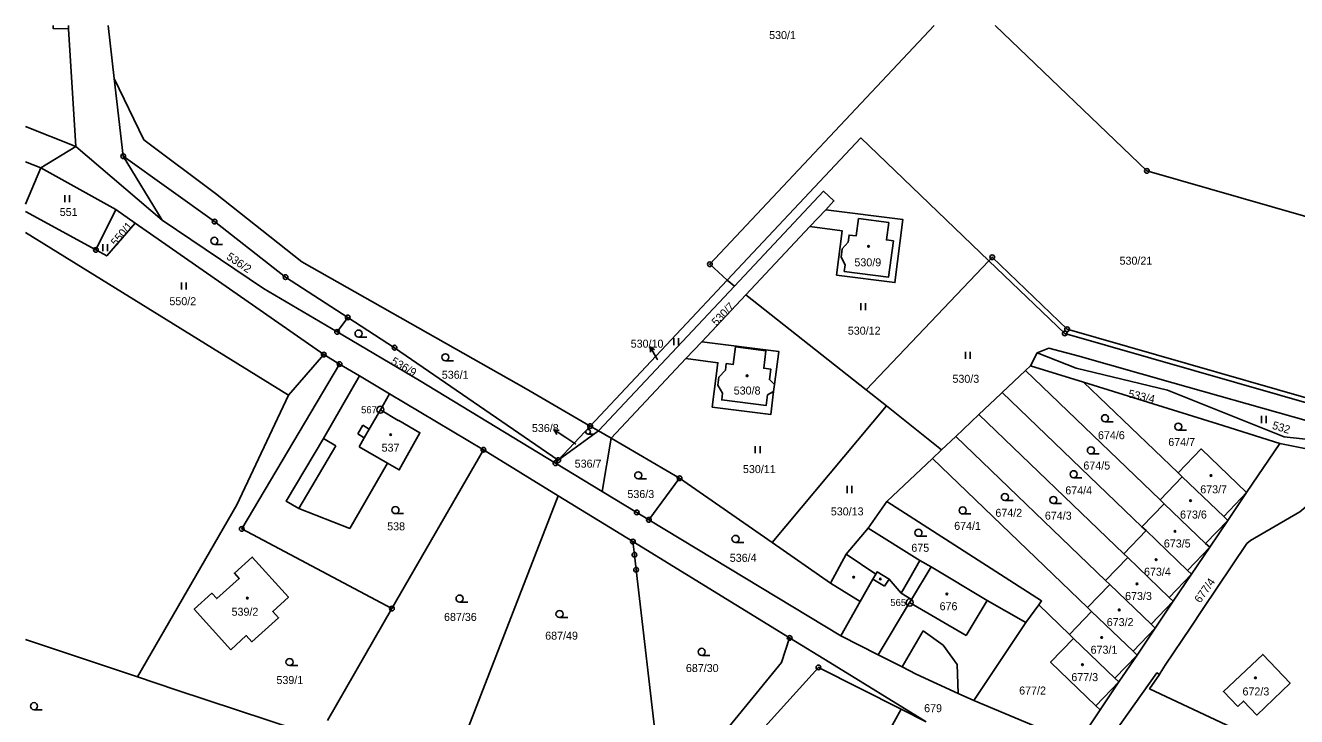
# Model space of a CAD drawing. Extents: x -749778 to -749372, y -967291 to -966955.
# Drawn here: x -749777.6 to -749507.7, y -967101.9 to -966955.1 of the extents above; entities that cross this region are included whole.
import ezdxf

# ---------------------------------------------------------------- set-up
doc = ezdxf.new("R2010")
doc.units = 0
for name, color, linetype in [('Hranice parcel', 7, 'Continuous'), ('Parcelní čísla', 7, 'Continuous'), ('Pop  PČ popisy', 7, 'Continuous'), ('Vnitřní kresba', 7, 'Continuous'), ('Značky bodu BP', 7, 'Continuous'), ('Značky budov', 7, 'Continuous'), ('Značky kultur', 7, 'Continuous')]:
    doc.layers.add(name, color=color, linetype=linetype)

msp = doc.modelspace()

# ---------------------------------------------------------------- linework, layer by layer
at = {"layer": 'Hranice parcel'}
for p, q in [((-749768.49, -966955.06), (-749768.51, -966955.82)), ((-749768.51, -966955.82), (-749766.93, -966980.78)), ((-749756.87, -966982.87), (-749758.78, -966966.32)), ((-749766.93, -966980.78), (-749777.63, -966976.54)), ((-749774.34, -966985.3), (-749766.93, -966980.78)), ((-749766.93, -966980.78), (-749748.6, -966996.42)), ((-749748.6, -966996.42), (-749756.87, -966982.87)), ((-749774.34, -966985.3), (-749777.63, -966984.05)), ((-749758.43, -966994.19), (-749774.34, -966985.3)), ((-749758.43, -966994.19), (-749762.66, -967002.76)), ((-749754.33, -966997.05), (-749758.43, -966994.19)), ((-749611.05, -966997.82), (-749607.66, -966994.22)), ((-749714.28, -967025), (-749754.33, -966997.05)), ((-749721.74, -967033.62), (-749777.63, -966999.06)), ((-749624.66, -967012.31), (-749611.05, -966997.82)), ((-749573, -967005.05), (-749599.06, -967032.48)), ((-749657.69, -967040.19), (-749628.61, -967009.22)), ((-749627.02, -967010.45), (-749655.92, -967041.22)), ((-749627.02, -967010.45), (-749628.61, -967009.22)), ((-749634, -967022.26), (-749624.66, -967012.31)), ((-749599.06, -967032.48), (-749624.66, -967012.31)), ((-749711.43, -967020.19), (-749709.16, -967017.1)), ((-749637.38, -967025.86), (-749634, -967022.26)), ((-749721.74, -967033.62), (-749714.28, -967025)), ((-749714.28, -967025), (-749710.9, -967027.02)), ((-749706.67, -967029.54), (-749710.9, -967027.02)), ((-749653.26, -967042.77), (-749637.38, -967025.86)), ((-749564.16, -967027.37), (-749562.74, -967024.63)), ((-749700.29, -967033.34), (-749706.67, -967029.54)), ((-749570.18, -967033.07), (-749565.25, -967028.4)), ((-749565.25, -967028.4), (-749564.16, -967027.37)), ((-749536.64, -967055.87), (-749565.25, -967028.4)), ((-749564.16, -967027.37), (-749552.89, -967030.87)), ((-749532.8, -967050.13), (-749552.89, -967030.87)), ((-749680.37, -967045.22), (-749700.29, -967033.34)), ((-749599.06, -967032.48), (-749594.75, -967035.91)), ((-749540.5, -967061.59), (-749570.18, -967033.07)), ((-749619.07, -967064.92), (-749594.75, -967035.91)), ((-749594.75, -967035.91), (-749583.06, -967045.24)), ((-749580.06, -967042.41), (-749575.13, -967037.74)), ((-749544.33, -967067.31), (-749575.13, -967037.74)), ((-749664.47, -967047.42), (-749657.69, -967040.19)), ((-749655.92, -967041.22), (-749657.69, -967040.19)), ((-749655.92, -967041.22), (-749664.47, -967047.42)), ((-749655.92, -967041.22), (-749653.26, -967042.77)), ((-749653.26, -967042.77), (-749655.12, -967054.12)), ((-749638.69, -967051.26), (-749653.26, -967042.77)), ((-749583.06, -967045.24), (-749580.06, -967042.41)), ((-749548.22, -967073.01), (-749580.06, -967042.41)), ((-749699.81, -967078.98), (-749680.37, -967045.22)), ((-749680.37, -967045.22), (-749664.5, -967054.98)), ((-749583.06, -967045.24), (-749585.01, -967047.08)), ((-749518.29, -967054.31), (-749511.23, -967043.86)), ((-749664.47, -967047.42), (-749665.08, -967048.07)), ((-749655.12, -967054.12), (-749665.08, -967048.07)), ((-749585.01, -967047.08), (-749594.68, -967056.22)), ((-749552.05, -967078.75), (-749585.01, -967047.08)), ((-749645.2, -967060.11), (-749638.69, -967051.26)), ((-749619.07, -967064.92), (-749638.69, -967051.26)), ((-749531.93, -967050.96), (-749536.64, -967055.87)), ((-749532.8, -967050.13), (-749531.93, -967050.96)), ((-749684.12, -967105.59), (-749664.5, -967054.98)), ((-749664.5, -967054.98), (-749648.62, -967064.74)), ((-749535.77, -967056.7), (-749540.5, -967061.59)), ((-749536.64, -967055.87), (-749535.77, -967056.7)), ((-749522.26, -967060.23), (-749518.29, -967054.31)), ((-749604.44, -967084.74), (-749645.2, -967060.11)), ((-749540.5, -967061.59), (-749539.64, -967062.41)), ((-749526.12, -967065.95), (-749522.26, -967060.23)), ((-749648.62, -967064.74), (-749615.32, -967085.21)), ((-749539.64, -967062.41), (-749544.33, -967067.31)), ((-749606.68, -967073.54), (-749619.07, -967064.92)), ((-749603.32, -967067.37), (-749606.68, -967073.54)), ((-749544.33, -967067.31), (-749543.47, -967068.14)), ((-749529.98, -967071.67), (-749526.12, -967065.95)), ((-749543.47, -967068.14), (-749548.22, -967073.01)), ((-749533.84, -967077.4), (-749529.98, -967071.67)), ((-749547.35, -967073.84), (-749552.05, -967078.75)), ((-749548.22, -967073.01), (-749547.35, -967073.84)), ((-749565.15, -967081.89), (-749562.42, -967078.16)), ((-749562.42, -967078.16), (-749555.87, -967084.45)), ((-749537.69, -967083.12), (-749533.84, -967077.4)), ((-749699.81, -967078.98), (-749713.49, -967102.74)), ((-749551.19, -967079.58), (-749555.87, -967084.45)), ((-749552.05, -967078.75), (-749551.19, -967079.58)), ((-749576.24, -967098.5), (-749565.15, -967081.89)), ((-749541.54, -967088.85), (-749537.69, -967083.12)), ((-749555.87, -967084.45), (-749555.02, -967085.29)), ((-749545.4, -967094.56), (-749541.54, -967088.85)), ((-749549.38, -967100.48), (-749545.4, -967094.56)), ((-749576.24, -967098.5), (-749554.23, -967107.67)), ((-749586.36, -967103.02), (-749591.67, -967100.33))]:
    msp.add_line(p, q, dxfattribs=at)
for points in [[(-749768.51, -966955.82), (-749771.73, -966955.75), (-749771.71, -966955.06)], [(-749758.78, -966966.32), (-749760.08, -966955.06)], [(-749628.61, -967009.22), (-749632.26, -967005.8), (-749584.62, -966955.06)], [(-749571.65, -966955.06), (-749539.45, -966985.97), (-749459.63, -967008.89), (-749477.4, -967037.32)], [(-749758.78, -966966.32), (-749752.45, -966979.37), (-749737.29, -966990.76), (-749718.94, -967005.3), (-749671.29, -967032.27), (-749657.69, -967040.19)], [(-749573, -967005.05), (-749600.19, -966978.95), (-749628.61, -967009.22)], [(-749756.87, -966982.87), (-749737.45, -966996.74), (-749722.38, -967008.55), (-749709.16, -967017.1)], [(-749777.63, -966993.01), (-749774.34, -966985.3)], [(-749607.66, -966994.22), (-749605.92, -966992.36), (-749608.11, -966990.31), (-749627.02, -967010.45)], [(-749762.66, -967002.76), (-749777.63, -966994.6)], [(-749611.05, -966997.82), (-749604.17, -966998.69), (-749605.37, -967008.12), (-749592.97, -967009.7), (-749591.26, -966996.3), (-749607.66, -966994.22)], [(-749762.66, -967002.76), (-749760.36, -967004.02), (-749754.33, -966997.05)], [(-749711.43, -967020.19), (-749727.04, -967010.95), (-749748.6, -966996.42)], [(-749573, -967005.05), (-749572.31, -967004.33), (-749556.39, -967019.6), (-749480.03, -967041.53), (-749477.4, -967037.32)], [(-749474.68, -967044.11), (-749556.9, -967020.49), (-749573, -967005.05)], [(-749709.16, -967017.1), (-749699.22, -967023.53), (-749664.47, -967047.42)], [(-749665.08, -967048.07), (-749693.94, -967030.54), (-749711.43, -967020.19)], [(-749637.38, -967025.86), (-749630.55, -967026.73), (-749631.75, -967036.16), (-749619.35, -967037.74), (-749618.72, -967032.84), (-749618.54, -967031.36), (-749617.64, -967024.34), (-749634, -967022.26)], [(-749562.74, -967024.63), (-749560.29, -967023.62), (-749554.11, -967025.29), (-749533.97, -967031.01), (-749482.86, -967045.42)], [(-749710.9, -967027.02), (-749731.68, -967062.04), (-749699.81, -967078.98)], [(-749562.74, -967024.63), (-749554.44, -967027.88), (-749535.11, -967032.59), (-749510.28, -967042.45), (-749482.86, -967045.42)], [(-749706.67, -967029.54), (-749714.33, -967042.83), (-749722.22, -967056.16), (-749719.59, -967057.72), (-749708.76, -967061.94), (-749700.71, -967048.1), (-749698.23, -967049.52), (-749693.83, -967041.62), (-749698.3, -967038.99), (-749698.47, -967039.04), (-749702.24, -967036.72), (-749700.29, -967033.34)], [(-749552.89, -967030.87), (-749524.47, -967039.74), (-749511.23, -967043.86)], [(-749753.84, -967093.49), (-749732.73, -967056.95), (-749721.74, -967033.62)], [(-749575.13, -967037.74), (-749570.49, -967033.35), (-749570.18, -967033.07)], [(-749518.29, -967054.31), (-749527.96, -967045.04), (-749532.8, -967050.13)], [(-749511.23, -967043.86), (-749503.78, -967045.37), (-749490.3, -967048.1), (-749484.05, -967051.31)], [(-749522.26, -967060.23), (-749523.13, -967059.41), (-749531.93, -967050.96)], [(-749456.84, -967065.27), (-749475.82, -967057.43), (-749489.74, -967052.51), (-749500.28, -967053.21), (-749501.83, -967053.4), (-749502.46, -967054.34), (-749503.87, -967055.82), (-749506.95, -967058.39), (-749517.45, -967064.49), (-749518.23, -967065.16), (-749527.61, -967079.16), (-749530.11, -967082.89), (-749535.6, -967090.98), (-749536.66, -967092.72), (-749536.81, -967092.95)], [(-749645.2, -967060.11), (-749647.8, -967058.54), (-749655.12, -967054.12)], [(-749594.68, -967056.22), (-749598.63, -967061.85), (-749603.32, -967067.37)], [(-749594.68, -967056.22), (-749561.83, -967077.35), (-749562.42, -967078.16)], [(-749526.12, -967065.95), (-749526.97, -967065.13), (-749535.77, -967056.7)], [(-749648.62, -967064.74), (-749648.3, -967067.53), (-749647.94, -967070.71), (-749643.43, -967109.15)], [(-749529.98, -967071.67), (-749530.84, -967070.85), (-749539.64, -967062.41)], [(-749603.32, -967067.37), (-749597.01, -967071.63), (-749596.76, -967071.19), (-749594.16, -967072.69), (-749591.62, -967075.7), (-749589.79, -967072.47), (-749587.69, -967068.76), (-749585.3, -967070.11), (-749573.36, -967077.28), (-749565.15, -967081.89)], [(-749734.04, -967087.7), (-749741.77, -967079.12), (-749738.02, -967075.7), (-749737, -967076.84), (-749732.23, -967072.54), (-749733.26, -967071.41), (-749729.47, -967068.01), (-749721.76, -967076.51), (-749725.09, -967079.58), (-749723.88, -967080.9), (-749729.51, -967086), (-749730.74, -967084.72), (-749734.04, -967087.7)], [(-749533.84, -967077.4), (-749534.69, -967076.58), (-749543.47, -967068.14)], [(-749606.68, -967073.54), (-749600.38, -967077.49), (-749604.44, -967084.74)], [(-749537.69, -967083.12), (-749538.56, -967082.3), (-749547.35, -967073.84)], [(-749541.54, -967088.85), (-749542.39, -967088.02), (-749551.19, -967079.58)], [(-749777.63, -967085.52), (-749753.84, -967093.49)], [(-749632.88, -967109.8), (-749617.06, -967090.42), (-749615.32, -967085.21)], [(-749615.32, -967085.21), (-749606.8, -967090.45), (-749586.36, -967103.02)], [(-749604.44, -967084.74), (-749596.53, -967088.77), (-749591.42, -967091.37), (-749588.45, -967092.89), (-749579.53, -967096.99), (-749576.24, -967098.5)], [(-749549.38, -967100.48), (-749550.27, -967099.62), (-749559.92, -967090.32), (-749555.02, -967085.29)], [(-749555.02, -967085.29), (-749546.27, -967093.74), (-749545.4, -967094.56)], [(-749520.16, -967099.8), (-749523.2, -967096.56), (-749514.83, -967088.7), (-749509.04, -967094.79), (-749516.12, -967101.59), (-749518.91, -967098.62), (-749520.16, -967099.8)], [(-749624.65, -967108.54), (-749609.2, -967091.46), (-749591.67, -967100.33)], [(-749716.74, -967108.38), (-749719.68, -967104.83), (-749745.68, -967096.2), (-749753.84, -967093.49)], [(-749536.81, -967092.95), (-749537.33, -967092.65), (-749549.42, -967109.68)], [(-749536.81, -967092.95), (-749538.87, -967096), (-749521.44, -967104.24), (-749491.04, -967118.52)], [(-749591.67, -967100.33), (-749597.57, -967111.08), (-749601.91, -967114.2), (-749600.64, -967116.26), (-749606.62, -967124.91)], [(-749554.23, -967107.67), (-749553.8, -967107.04), (-749549.38, -967100.48)]]:
    msp.add_lwpolyline(points, dxfattribs=at)
at = {"layer": 'Pop  PČ popisy'}
for p, q in [((-749643.44, -967025.94), (-749644.94, -967023.34)), ((-749644.94, -967023.34), (-749644.01, -967023.96)), ((-749644.94, -967023.34), (-749644.87, -967024.46)), ((-749643.35, -967026.09), (-749643.44, -967025.94)), ((-749662.84, -967042.65), (-749665.36, -967041.02)), ((-749665.36, -967041.02), (-749664.24, -967041.14)), ((-749665.36, -967041.02), (-749664.79, -967041.98)), ((-749660.71, -967044.04), (-749662.84, -967042.65))]:
    msp.add_line(p, q, dxfattribs=at)
at = {"layer": 'Vnitřní kresba'}
for p, q in [((-749704.61, -967040.83), (-749702.24, -967036.72)), ((-749707.06, -967041.87), (-749706, -967040.03)), ((-749706, -967040.03), (-749704.61, -967040.83)), ((-749714.33, -967042.83), (-749711.7, -967044.39)), ((-749705.67, -967042.67), (-749707.06, -967041.87)), ((-749706.78, -967044.6), (-749705.67, -967042.67)), ((-749704.61, -967040.83), (-749705.67, -967042.67)), ((-749711.7, -967044.39), (-749719.59, -967057.72)), ((-749700.71, -967048.1), (-749706.78, -967044.6)), ((-749518.29, -967054.31), (-749523.13, -967059.41)), ((-749598.63, -967061.85), (-749587.69, -967068.76)), ((-749522.26, -967060.23), (-749526.97, -967065.13)), ((-749526.12, -967065.95), (-749530.84, -967070.85)), ((-749585.3, -967070.11), (-749589.45, -967077.04)), ((-749600.38, -967077.49), (-749597.64, -967072.72)), ((-749597.64, -967072.72), (-749597.01, -967071.63)), ((-749597.64, -967072.72), (-749595.16, -967074.22)), ((-749595.16, -967074.22), (-749594.16, -967072.69)), ((-749529.98, -967071.67), (-749534.69, -967076.58)), ((-749596.53, -967088.77), (-749589.84, -967077.68)), ((-749589.45, -967077.04), (-749591.62, -967075.7)), ((-749589.45, -967077.04), (-749589.84, -967077.68)), ((-749589.84, -967077.68), (-749577.8, -967084.66)), ((-749577.8, -967084.66), (-749573.36, -967077.28)), ((-749533.84, -967077.4), (-749538.56, -967082.3)), ((-749591.42, -967091.37), (-749586.97, -967083.68)), ((-749586.97, -967083.68), (-749582.71, -967086.75)), ((-749537.69, -967083.12), (-749542.39, -967088.02)), ((-749582.71, -967086.75), (-749579.76, -967090.87)), ((-749541.54, -967088.85), (-749546.27, -967093.74)), ((-749579.76, -967090.87), (-749579.53, -967096.99)), ((-749545.4, -967094.56), (-749550.27, -967099.62))]:
    msp.add_line(p, q, dxfattribs=at)
for points in [[(-749600.72, -966996.1), (-749594.29, -966996.94), (-749594.78, -967000.65), (-749593.29, -967000.84), (-749594.3, -967008.54), (-749603.72, -967007.34), (-749603.55, -967005.96), (-749604.36, -967004.27), (-749604.15, -967002.52), (-749602.91, -967001.13), (-749602.71, -966999.6), (-749601.22, -966999.79), (-749600.72, -966996.1)], [(-749626.82, -967023.37), (-749627.29, -967027.09), (-749628.78, -967026.9), (-749628.95, -967028.28), (-749630.36, -967029.77), (-749630.59, -967031.47), (-749629.6, -967033.23), (-749629.75, -967034.63), (-749620.32, -967035.84), (-749620.04, -967033.56), (-749618.72, -967032.84)], [(-749626.82, -967023.37), (-749620.37, -967024.18), (-749620.84, -967027.91), (-749619.35, -967028.09), (-749619.62, -967030.3), (-749618.54, -967031.36)]]:
    msp.add_lwpolyline(points, dxfattribs=at)
at = {"layer": 'Značky bodu BP'}
for centre, radius in [((-749756.87, -966982.87), 0.5), ((-749756.87, -966982.87), 0.0303), ((-749539.45, -966985.97), 0.5), ((-749539.45, -966985.97), 0.0303), ((-749737.45, -966996.74), 0.5), ((-749737.45, -966996.74), 0.0303), ((-749762.66, -967002.76), 0.5), ((-749762.66, -967002.76), 0.0303), ((-749632.26, -967005.8), 0.5), ((-749572.31, -967004.33), 0.5), ((-749572.31, -967004.33), 0.0303), ((-749722.38, -967008.55), 0.5), ((-749632.26, -967005.8), 0.0303), ((-749722.38, -967008.55), 0.0303), ((-749709.16, -967017.1), 0.5), ((-749709.16, -967017.1), 0.0303), ((-749711.43, -967020.19), 0.5), ((-749711.43, -967020.19), 0.0303), ((-749556.9, -967020.49), 0.5), ((-749556.9, -967020.49), 0.0303), ((-749556.39, -967019.6), 0.5), ((-749556.39, -967019.6), 0.0303), ((-749699.22, -967023.53), 0.5), ((-749699.22, -967023.53), 0.0303), ((-749714.28, -967025), 0.5), ((-749714.28, -967025), 0.0303), ((-749710.9, -967027.02), 0.5), ((-749710.9, -967027.02), 0.0303), ((-749702.24, -967036.72), 0.75), ((-749702.24, -967036.72), 0.03), ((-749657.69, -967040.19), 0.5), ((-749657.69, -967040.19), 0.0303), ((-749680.37, -967045.22), 0.5), ((-749680.37, -967045.22), 0.0303), ((-749665.08, -967048.07), 0.5), ((-749665.08, -967048.07), 0.0303), ((-749664.47, -967047.42), 0.5), ((-749664.47, -967047.42), 0.0303), ((-749638.69, -967051.26), 0.5), ((-749638.69, -967051.26), 0.0303), ((-749647.8, -967058.54), 0.5), ((-749647.8, -967058.54), 0.0303), ((-749731.68, -967062.04), 0.5), ((-749731.68, -967062.04), 0.0303), ((-749645.2, -967060.11), 0.5), ((-749645.2, -967060.11), 0.0303), ((-749648.62, -967064.74), 0.5), ((-749648.62, -967064.74), 0.0303), ((-749648.3, -967067.53), 0.5), ((-749648.3, -967067.53), 0.0303), ((-749647.94, -967070.71), 0.5), ((-749647.94, -967070.71), 0.0303), ((-749589.84, -967077.68), 0.75), ((-749589.84, -967077.68), 0.03), ((-749699.81, -967078.98), 0.5), ((-749699.81, -967078.98), 0.0303), ((-749615.32, -967085.21), 0.5), ((-749615.32, -967085.21), 0.0303), ((-749609.2, -967091.46), 0.5), ((-749609.2, -967091.46), 0.0303)]:
    msp.add_circle(centre, radius, dxfattribs=at)
at = {"layer": 'Značky budov'}
for centre in [(-749598.56, -967002.01), (-749624.36, -967029.5), (-749700.06, -967042), (-749525.83, -967050.7), (-749530.18, -967056.03), (-749533.49, -967062.55), (-749537.49, -967068.59), (-749601.74, -967072.29), (-749596.06, -967072.68), (-749541.55, -967073.72), (-749730.5, -967076.75), (-749581.93, -967075.87), (-749545.33, -967079.25), (-749549.07, -967085.11), (-749553.14, -967090.89), (-749516.39, -967093.68)]:
    msp.add_circle(centre, 0.175, dxfattribs=at)
at = {"layer": 'Značky kultur'}
for p, q in [((-749769.29, -966992.6), (-749769.29, -966991.1)), ((-749768.29, -966992.6), (-749768.29, -966991.1)), ((-749761.17, -967003.05), (-749761.17, -967001.55)), ((-749760.17, -967003.05), (-749760.17, -967001.55)), ((-749737.5, -967001.58), (-749735.75, -967001.58)), ((-749744.47, -967011.15), (-749744.47, -967009.65)), ((-749743.47, -967011.15), (-749743.47, -967009.65)), ((-749600.22, -967015.55), (-749600.22, -967014.05)), ((-749599.22, -967015.55), (-749599.22, -967014.05)), ((-749706.88, -967021.28), (-749705.13, -967021.28)), ((-749639.94, -967023.01), (-749639.94, -967021.51)), ((-749638.94, -967023.01), (-749638.94, -967021.51)), ((-749688.44, -967026.32), (-749686.69, -967026.32)), ((-749577.98, -967025.9), (-749577.98, -967024.4)), ((-749576.98, -967025.9), (-749576.98, -967024.4)), ((-749548.34, -967039.27), (-749546.59, -967039.27)), ((-749515.1, -967039.54), (-749515.1, -967038.04)), ((-749514.1, -967039.54), (-749514.1, -967038.04)), ((-749658.11, -967041.89), (-749656.94, -967041.89)), ((-749532.79, -967041.06), (-749531.04, -967041.06)), ((-749622.62, -967045.93), (-749622.62, -967044.43)), ((-749621.62, -967045.93), (-749621.62, -967044.43)), ((-749551.35, -967046.12), (-749549.6, -967046.12)), ((-749555.02, -967051.17), (-749553.27, -967051.17)), ((-749647.48, -967051.41), (-749645.73, -967051.41)), ((-749603.1, -967054.42), (-749603.1, -967052.92)), ((-749602.1, -967054.42), (-749602.1, -967052.92)), ((-749569.61, -967056.02), (-749567.86, -967056.02)), ((-749559.31, -967056.64), (-749557.56, -967056.64)), ((-749699.05, -967058.8), (-749697.3, -967058.8)), ((-749578.57, -967058.86), (-749576.82, -967058.86)), ((-749587.97, -967063.61), (-749586.22, -967063.61)), ((-749626.82, -967064.91), (-749625.07, -967064.91)), ((-749685.43, -967077.59), (-749683.68, -967077.59)), ((-749664.2, -967080.88), (-749662.45, -967080.88)), ((-749634, -967088.91), (-749632.25, -967088.91)), ((-749721.54, -967091.08), (-749719.79, -967091.08)), ((-749775.8, -967100.45), (-749774.05, -967100.45))]:
    msp.add_line(p, q, dxfattribs=at)
for centre, radius in [((-749737.5, -967000.83), 0.75), ((-749706.88, -967020.53), 0.75), ((-749688.44, -967025.57), 0.75), ((-749548.34, -967038.52), 0.75), ((-749532.79, -967040.31), 0.75), ((-749658.12, -967041.39), 0.502), ((-749551.35, -967045.37), 0.75), ((-749647.48, -967050.66), 0.75), ((-749555.02, -967050.42), 0.75), ((-749569.61, -967055.27), 0.75), ((-749559.31, -967055.89), 0.75), ((-749699.05, -967058.05), 0.75), ((-749578.57, -967058.11), 0.75), ((-749587.97, -967062.86), 0.75), ((-749626.82, -967064.16), 0.75), ((-749685.43, -967076.84), 0.75), ((-749664.2, -967080.13), 0.75), ((-749634, -967088.16), 0.75), ((-749721.54, -967090.33), 0.75), ((-749775.8, -967099.7), 0.75)]:
    msp.add_circle(centre, radius, dxfattribs=at)

# ---------------------------------------------------------------- texts
at = {"layer": 'Parcelní čísla'}
for s, p in [('530/1', (-749619.68, -966957.96)), ('551', (-749770.34, -966995.55)), ('530/9', (-749601.57, -967006.25)), ('530/21', (-749545.26, -967005.9)), ('550/2', (-749747.05, -967014.51)), ('530/12', (-749602.97, -967020.77)), ('530/10', (-749649.08, -967023.53)), ('536/1', (-749689.2, -967030.13)), ('530/3', (-749580.75, -967030.99)), ('530/8', (-749627.2, -967033.49)), ('536/8', (-749670.06, -967041.45)), ('674/6', (-749549.84, -967042.98)), ('674/7', (-749534.91, -967044.42)), ('537', (-749701.98, -967045.62)), ('536/7', (-749660.98, -967049.02)), ('530/11', (-749625.24, -967050.18)), ('674/5', (-749552.94, -967049.42)), ('536/3', (-749649.78, -967055.48)), ('674/4', (-749556.78, -967054.69)), ('673/7', (-749528.12, -967054.48)), ('530/13', (-749606.58, -967059.17)), ('674/2', (-749571.63, -967059.47)), ('674/3', (-749561.12, -967060.07)), ('673/6', (-749532.41, -967059.84)), ('538', (-749700.8, -967062.34)), ('674/1', (-749580.38, -967062.24)), ('673/5', (-749535.85, -967065.98)), ('536/4', (-749628.04, -967069.03)), ('675', (-749589.48, -967066.9)), ('673/4', (-749540.06, -967071.99)), ('673/3', (-749544.08, -967077.14)), ('676', (-749583.48, -967079.32)), ('539/2', (-749733.85, -967080.49)), ('687/36', (-749688.73, -967081.59)), ('673/2', (-749547.98, -967082.69)), ('687/49', (-749667.24, -967085.57)), ('673/1', (-749551.41, -967088.56)), ('687/30', (-749637.36, -967092.45)), ('539/1', (-749724.32, -967095)), ('677/3', (-749555.5, -967094.38)), ('677/2', (-749566.58, -967097.23)), ('672/3', (-749519.15, -967097.42)), ('679', (-749586.76, -967100.98))]:
    msp.add_text(s, height=1.7, dxfattribs=at).set_placement(p)
for s, rotation, p in [('550/1', 50, (-749758.37, -967002.08)), ('536/2', 326, (-749735.08, -967004.58)), ('530/7', 46, (-749630.86, -967019.02)), ('536/9', 330, (-749700.13, -967026.89)), ('533/4', 347, (-749543.53, -967034.06)), ('532', 343, (-749512.97, -967040.74)), ('677/4', 55, (-749528.12, -967077.92))]:
    msp.add_text(s, height=1.7, rotation=rotation, dxfattribs=at).set_placement(p)
at = {"layer": 'Značky bodu BP'}
for s, p in [('567', (-749706.34, -967037.47)), ('565', (-749593.94, -967078.43))]:
    msp.add_text(s, height=1.5, dxfattribs=at).set_placement(p)

doc.saveas('drawing.dxf')
